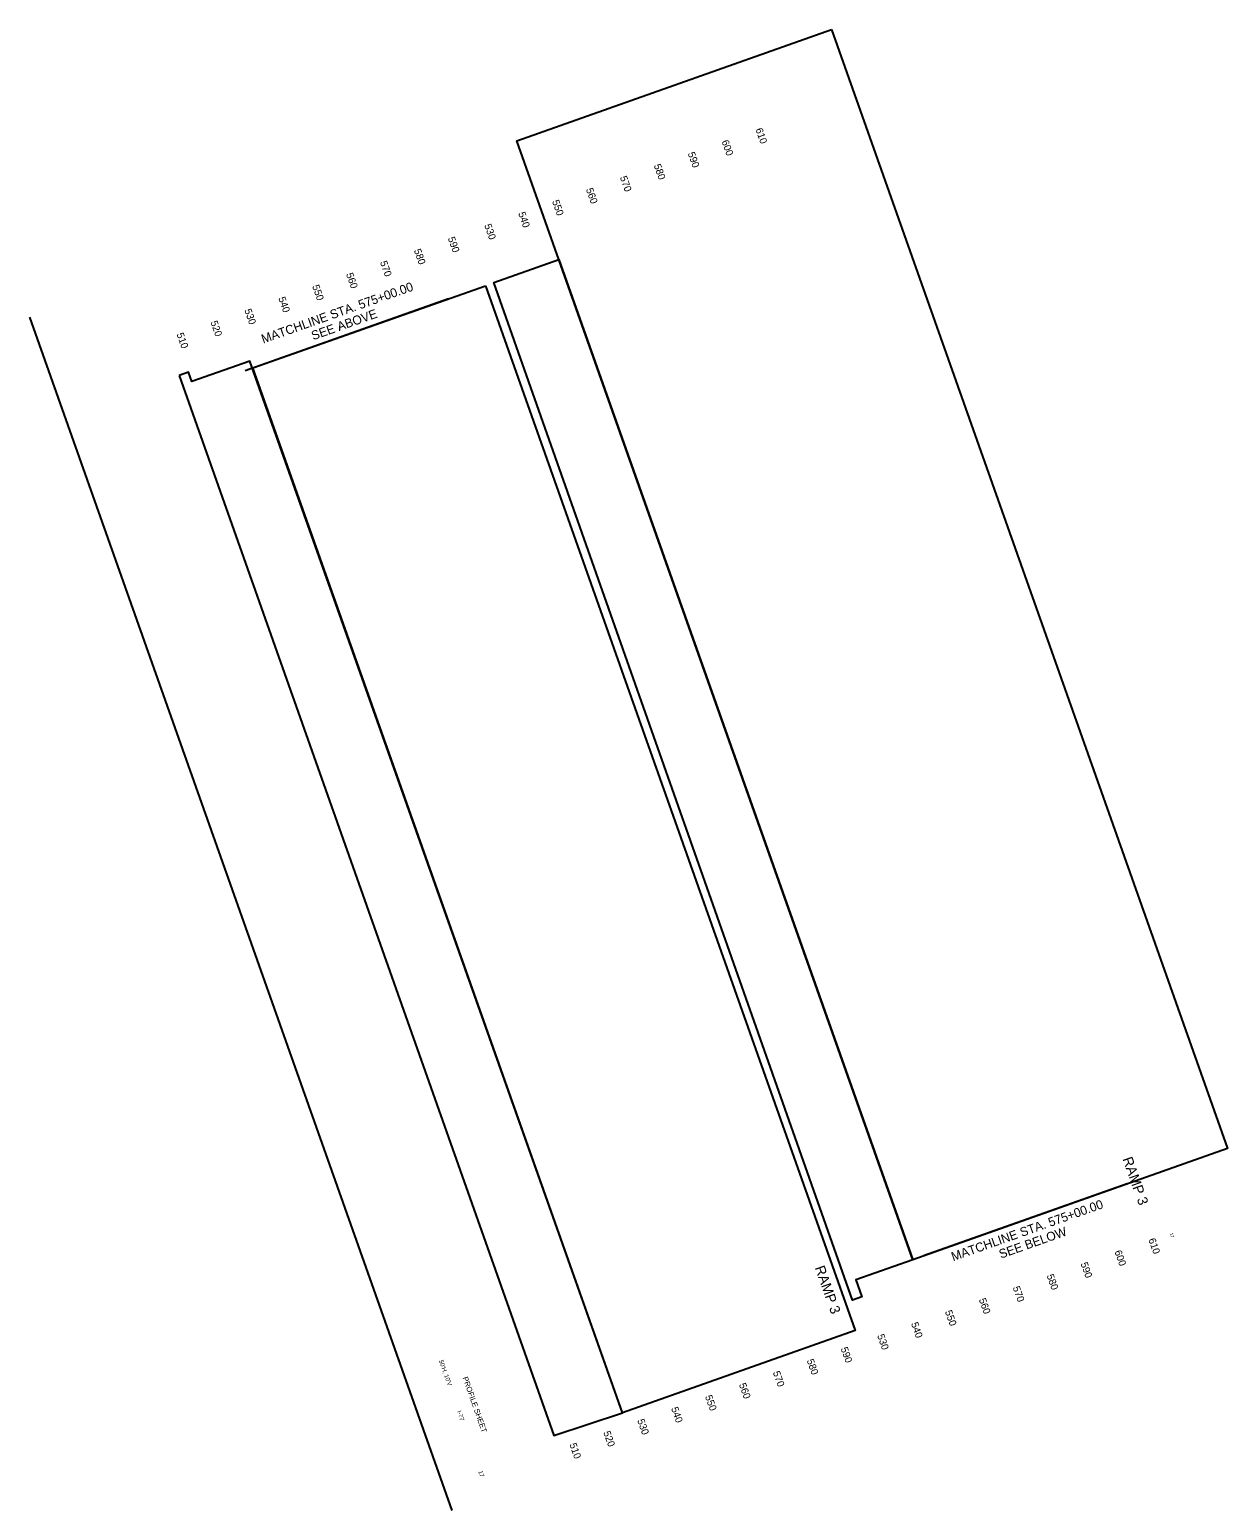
# Model space of a CAD drawing. Extents: x 1990416 to 1992081, y 1125738 to 1127797.
import ezdxf

# ---------------------------------------------------------------- set-up
doc = ezdxf.new("R2010")
doc.units = 0
for name, color, linetype in [('RD_DDB_ElevTX', 7, 'Continuous'), ('RD_DDB_Profile_Lbl', 7, 'Continuous'), ('RD_DDB_Profile_PR', 7, 'Continuous')]:
    doc.layers.add(name, color=color, linetype=linetype)

msp = doc.modelspace()

# ---------------------------------------------------------------- linework, layer by layer
at = {"layer": 'RD_DDB_ElevTX'}
msp.add_line((1990415.9, 1127397.5), (1991002.8, 1125738.3), dxfattribs=at)
at = {"layer": 'RD_DDB_Profile_Lbl'}
for points in [[(1991530.5, 1127797.2), (1992080.9, 1126241.5), (1991643.5, 1126086.8), (1991093.2, 1127642.5)], [(1991151.6, 1127477.4), (1991643.5, 1126086.8), (1991564.3, 1126058.8), (1991572.7, 1126035.2), (1991559.6, 1126030.4), (1991551.5, 1126054.2), (1991061.4, 1127445.4)], [(1991049.5, 1127441.2), (1991563.5, 1125988.4), (1991240, 1125874), (1990726.1, 1127326.8)], [(1990623.6, 1127316.5), (1991144.6, 1125842.3), (1991240, 1125874), (1990721.8, 1127336.4), (1990641.2, 1127307.9), (1990636.5, 1127321.1)]]:
    msp.add_lwpolyline(points, close=True, dxfattribs=at)
at = {"layer": 'RD_DDB_Profile_PR'}
for p, q in [((1990998.2, 1127423.1), (1990715.4, 1127323)), ((1991941.4, 1126192.2), (1991658.6, 1126092.1))]:
    msp.add_line(p, q, dxfattribs=at)

# ---------------------------------------------------------------- texts
at = {"layer": 'RD_DDB_ElevTX'}
for s, height, p in [('610', 10, (1991424.8, 1127658.5)), ('600', 10, (1991377.7, 1127641.8)), ('590', 10, (1991330.6, 1127625.2)), ('570', 10, (1991236.3, 1127591.8)), ('580', 10, (1991283.4, 1127608.5)), ('560', 10, (1991189.1, 1127575.1)), ('550', 10, (1991142, 1127558.5)), ('540', 10, (1991094.9, 1127541.8)), ('590', 10, (1990997.1, 1127507.2)), ('530', 10, (1991047.7, 1127525.1)), ('580', 10, (1990949.9, 1127490.5)), ('570', 10, (1990902.8, 1127473.8)), ('560', 10, (1990855.6, 1127457.2)), ('540', 10, (1990761.4, 1127423.8)), ('550', 10, (1990808.5, 1127440.5)), ('530', 10, (1990714.2, 1127407.1)), ('520', 10, (1990667.1, 1127390.5)), ('510', 10, (1990620, 1127373.8)), ('RAMP 3', 14, (1991935, 1126227)), ('610', 10, (1991971, 1126114.8)), ('17', 4.5, (1992000.6, 1126123.3)), ('600', 10, (1991923.8, 1126098.1)), ('RAMP 3', 14, (1991507.2, 1126075.7)), ('580', 10, (1991829.5, 1126064.8)), ('590', 10, (1991876.7, 1126081.4)), ('570', 10, (1991782.4, 1126048.1)), ('560', 10, (1991735.3, 1126031.4)), ('550', 10, (1991688.1, 1126014.7)), ('540', 10, (1991641, 1125998)), ('590', 10, (1991543.2, 1125963.4)), ('530', 10, (1991593.9, 1125981.4)), ("50'H, 10'V", 6, (1990984.9, 1125946.3)), ('580', 10, (1991496, 1125946.8)), ('PROFILE SHEET', 7.5, (1991017.6, 1125922.7)), ('570', 10, (1991448.9, 1125930.1)), ('560', 10, (1991401.8, 1125913.4)), ('540', 10, (1991307.5, 1125880.1)), ('550', 10, (1991354.6, 1125896.7)), ('I-77', 6, (1991009.9, 1125875.8)), ('530', 10, (1991260.4, 1125863.4)), ('520', 10, (1991213.2, 1125846.7)), ('510', 10, (1991166.1, 1125830)), ('17', 6, (1991039.4, 1125792.4))]:
    msp.add_text(s, height=height, rotation=289.482, dxfattribs=at).set_placement(p)
at = {"layer": 'RD_DDB_Profile_PR'}
for s, p in [('MATCHLINE STA. 575+00.00', (1990740.6, 1127360.6)), ('SEE ABOVE', (1990810.1, 1127365.3)), ('MATCHLINE STA. 575+00.00', (1991699.7, 1126084.7)), ('SEE BELOW', (1991766, 1126088.2))]:
    msp.add_text(s, height=12.5, rotation=19.482, dxfattribs=at).set_placement(p)

doc.saveas('drawing.dxf')
